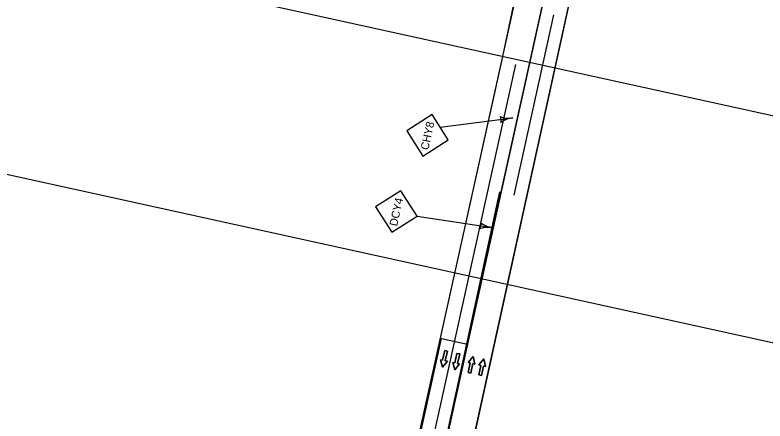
# Model space of a CAD drawing. Extents: x 14104283 to 14128447, y 8633203 to 8671666.
# Drawn here: x 14107271 to 14107946, y 8638411 to 8638776 of the extents above; entities that cross this region are included whole.
import ezdxf

# ---------------------------------------------------------------- set-up
doc = ezdxf.new("R2010")
doc.units = 0
for name, color, linetype in [('Cell', 7, 'Continuous'), ('Default', 7, 'Continuous'), ('dsnNonPlotable', 7, 'Continuous'), ('dsnPaintExistingBrokenLaneLineWhite', 7, 'Continuous'), ('dsnPaintExistingDoubleCenterYellow', 7, 'Continuous'), ('dsnPaintExistingEdgeLineRightWhite', 7, 'Continuous'), ('dsnPaintPlaceDoubleCenterLineYellow', 7, 'Continuous'), ('dsnStdLabel', 7, 'Continuous')]:
    doc.layers.add(name, color=color, linetype=linetype)

msp = doc.modelspace()

# ---------------------------------------------------------------- linework, layer by layer
at = {"layer": 'Cell'}
for points in [[(14107657.91, 8638474.05), (14107660.35, 8638473.52), (14107658.49, 8638464.97), (14107660.32, 8638464.57), (14107655.93, 8638459.13), (14107654.21, 8638465.9), (14107656.04, 8638465.5)], [(14107668.97, 8638471.62), (14107671.41, 8638471.09), (14107669.55, 8638462.54), (14107671.38, 8638462.14), (14107666.99, 8638456.7), (14107665.27, 8638463.47), (14107667.1, 8638463.07)], [(14107681.43, 8638453.88), (14107678.99, 8638454.41), (14107680.86, 8638462.96), (14107679.03, 8638463.36), (14107683.41, 8638468.8), (14107685.13, 8638462.03), (14107683.3, 8638462.43)], [(14107691.04, 8638451.68), (14107688.59, 8638452.22), (14107690.46, 8638460.76), (14107688.63, 8638461.16), (14107693.01, 8638466.6), (14107694.73, 8638459.83), (14107692.9, 8638460.23)]]:
    msp.add_lwpolyline(points, close=True, dxfattribs=at)
for points in [[(14107656.04, 8638465.5), (14107654.21, 8638465.9), (14107655.93, 8638459.13), (14107660.32, 8638464.57), (14107658.49, 8638464.97), (14107660.35, 8638473.52), (14107657.91, 8638474.05), (14107656.04, 8638465.5)], [(14107667.1, 8638463.07), (14107665.27, 8638463.47), (14107666.99, 8638456.7), (14107671.38, 8638462.14), (14107669.55, 8638462.54), (14107671.41, 8638471.09), (14107668.97, 8638471.62), (14107667.1, 8638463.07)], [(14107683.3, 8638462.43), (14107685.13, 8638462.03), (14107683.41, 8638468.8), (14107679.03, 8638463.36), (14107680.86, 8638462.96), (14107678.99, 8638454.41), (14107681.43, 8638453.88), (14107683.3, 8638462.43)], [(14107692.9, 8638460.23), (14107694.73, 8638459.83), (14107693.01, 8638466.6), (14107688.63, 8638461.16), (14107690.46, 8638460.76), (14107688.59, 8638452.22), (14107691.04, 8638451.68), (14107692.9, 8638460.23)]]:
    msp.add_lwpolyline(points, dxfattribs=at)
at = {"layer": 'Default'}
for p, q in [((14107781.69, 8639064), (14107653.91, 8638485.4)), ((14107678.52, 8638479.96), (14107806.31, 8639058.6)), ((14107653.91, 8638485.4), (14107678.52, 8638479.96))]:
    msp.add_line(p, q, dxfattribs=at)
for points in [[(14107649.23, 8638236.01), (14107828.56, 8639053.71), (14107806.31, 8639058.6), (14107625.69, 8638240.73)], [(14107392.92, 8637186.73), (14107369.48, 8637191.91), (14107655.09, 8638485.14), (14107678.52, 8638479.96)]]:
    msp.add_lwpolyline(points, close=True, dxfattribs=at)
at = {"layer": 'dsnNonPlotable'}
for points in [[(14107218.44, 8638642.33), (14107554.83, 8640173.31), (14108541.3, 8639956.56), (14108204.91, 8638425.58)], [(14106924.98, 8637306.69), (14107261.36, 8638837.67), (14108247.83, 8638620.92), (14107911.44, 8637089.94)]]:
    msp.add_lwpolyline(points, close=True, dxfattribs=at)
at = {"layer": 'dsnPaintExistingBrokenLaneLineWhite'}
for p, q in [((14107720.43, 8638614.09), (14107756.2, 8638776.05)), ((14107381.2, 8637189.32), (14107721.79, 8638731.54))]:
    msp.add_line(p, q, dxfattribs=at)
at = {"layer": 'dsnPaintExistingDoubleCenterYellow'}
msp.add_line((14107435.78, 8637377.61), (14107677.97, 8638480.08), dxfattribs=at)
at = {"layer": 'dsnPaintExistingEdgeLineRightWhite'}
for p, q in [((14107468.79, 8637415.99), (14107828.52, 8639053.57)), ((14107708.89, 8638734.37), (14107415.88, 8637407.61))]:
    msp.add_line(p, q, dxfattribs=at)
msp.add_lwpolyline([(14107752.01, 8638929.68), (14107727.67, 8638822.93), (14107708.89, 8638734.37)], dxfattribs=at)
at = {"layer": 'dsnPaintPlaceDoubleCenterLineYellow'}
msp.add_line((14107677.97, 8638480.08), (14107707.52, 8638617.05), dxfattribs=at)
at = {"layer": 'dsnStdLabel'}
for p, q in [((14107653.87, 8638675.06), (14107719.14, 8638683.54)), ((14107633.05, 8638595.14), (14107700.77, 8638584.74))]:
    msp.add_line(p, q, dxfattribs=at)
for points in [[(14107638.4, 8638649.14), (14107661.15, 8638663.69), (14107646.6, 8638686.43), (14107623.85, 8638671.88)], [(14107610.31, 8638580.59), (14107633.05, 8638595.14), (14107618.5, 8638617.88), (14107595.76, 8638603.33)]]:
    msp.add_lwpolyline(points, close=True, dxfattribs=at)
for centre, radius, start, end in [((14107716.03, 8638706.16), 22.95, 249.12679, 277.19809), ((14107699.82, 8638680.98), 8.86, 349.46377, 24.93222), ((14107721.78, 8638660.62), 22.95, 97.19794, 125.2692), ((14107681.75, 8638587.66), 8.86, 333.54003, 9.00847), ((14107697.29, 8638562.06), 22.95, 81.2742, 109.34546), ((14107704.25, 8638607.43), 22.95, 233.20304, 261.27435)]:
    msp.add_arc(centre, radius, start, end, dxfattribs=at)

# ---------------------------------------------------------------- texts
for s, p in [('CHY8', (14107643.19, 8638654.12)), ('DCY4', (14107615.1, 8638585.59))]:
    msp.add_text(s, height=7.2, rotation=77.60784, dxfattribs=at).set_placement(p)

doc.saveas('drawing.dxf')
